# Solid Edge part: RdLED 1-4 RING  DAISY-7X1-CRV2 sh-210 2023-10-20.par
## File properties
Author: robert.pupel
Template: iso metric part.par
Last saved by: robert.pupel
Revision: 5
Application: Solid Edge
Gęstość: 0.000 kg/m^3
Dokładność: 0.990
Username: robert.pupel
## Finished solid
Body 1: solid body, 2455 faces, 6322 edges, 4178 vertices.
  Faces by surface: plane 1986, cylinder 357, swept 80, sphere 16, cone 8, spline 8
  Edges by curve: line 4776, spline 488, curve on surface 480, circle 290, ellipse 288
Bounding box of the edges (mm; curved faces can reach further): 74.146 x 4.330 x 269.407, from (-37.073, -2.73, -134.7035) to (37.073, 1.6, 134.7035).
Cylindrical faces by radius (mm): R0.0495 x8, R0.0647 x16, R0.0649 x16, R0.1 x16, R0.1164 x8, R0.1314 x32, R0.1729 x8, R0.2289 x8, R0.47 x16, R0.5 x112, R0.6 x8, R0.625 x8, R0.7253 x4, R0.75 x16, R0.9711 x4, R1.0277 x8, R1.05 x13, R1.1475 x8, R1.1477 x8, R1.25 x14, R1.305 x8, R1.3069 x8, R1.65 x6, R1.6502 x2, R165.9999 x1, R194 x1
Conical faces (half-angle, radius in mm at the cone's reference point): 36.872 deg R0.8536 x8
Spherical faces by radius (mm): R0.5 x16
Planar faces by outward normal: +x 75, +y 25, +z 66, -x 77, -y 253, -z 66, oblique 1424
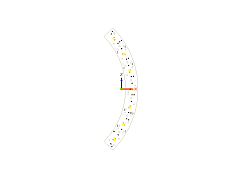
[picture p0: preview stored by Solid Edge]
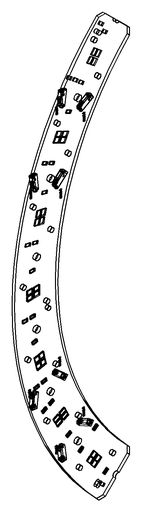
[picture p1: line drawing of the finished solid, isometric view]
